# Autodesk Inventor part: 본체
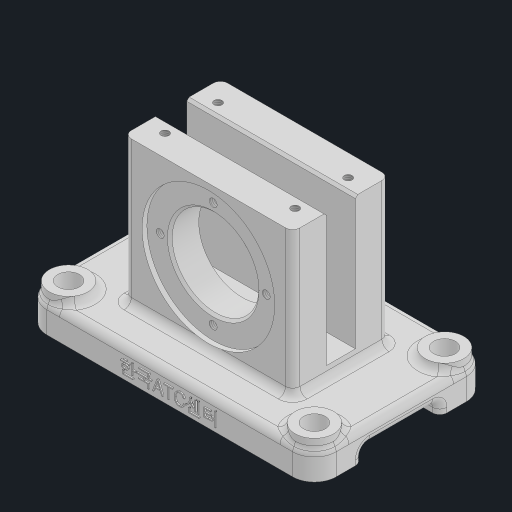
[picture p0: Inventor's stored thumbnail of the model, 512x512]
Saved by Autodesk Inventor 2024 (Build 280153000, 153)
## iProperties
Created: 2025-04
Part Number: 본체
Material: 일반
Document SubType Name: Modeling
Designer: kh_501
Density: 1 g/cm^3
Appearance: 기본값
Author: kh_501
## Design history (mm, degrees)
sketch "스케치1"
  geometry: L1 (-36, 60)-(36, 60); L2 (36, 60)-(36, -60); L3 (36, -60)-(-36, -60); L4 (-36, -60)-(-36, 60); L5 (-36, 60)-(36, -60); L6 (36, 60)-(-36, -60); 1 further point
  constraints: 12 end point, 2 midpoint, 2 parallel, 1 horizontal, 1 perpendicular
  dimensions: "d0" = 72 distance of L2.end L3.end; "d1" = 120 distance of L1.end L2.end
extrude "돌출1" new body sketch "스케치1" distance "d2" = 12; taper "d3" = 0 deg
sketch "스케치2"
  geometry: L1 (20, -35)-(-20, -35); L2 (-20, -35)-(-20, 35); L3 (-20, 35)-(20, 35); L4 (20, 35)-(20, -35); L5 (20, -35)-(-20, 35); L6 (-20, -35)-(20, 35); 1 further point
  constraints: 12 end point, 2 midpoint, 2 parallel, 1 horizontal, 1 perpendicular
  dimensions: "d4" = 40 distance of L2.end L3.end; "d5" = 70 distance of L1.end L2.end
extrude "돌출2" join sketch "스케치2" distance "d6" = 60; taper "d7" = 0 deg
sketch "스케치3"
  geometry: L1 (6, -35)-(-6, -35); L2 (-6, -35)-(-6, 35); L3 (-6, 35)-(6, 35); L4 (6, 35)-(6, -35); L5 (6, -35)-(-6, 35); L6 (-6, -35)-(6, 35); 1 further point
  constraints: 12 end point, 2 midpoint, 2 parallel, 1 horizontal, 1 perpendicular
  dimensions: "d8" = 12 distance of L2.end L3.end; "d9" = 70 distance of L1.end L2.end
extrude "돌출3" cut sketch "스케치3" distance "d10" = 55; taper "d11" = 0 deg
fillet "모깎기1" dims "d12" = 9
sketch "스케치4"
  geometry: C1 r 8 at (-27, -51); C2 r 8 at (27, -51); C3 r 8 at (27, 51); C4 r 8 at (-27, 51); 5 further points
  constraints: 4 centre point, 4 coincident, 2 horizontal alignment, 2 vertical alignment
  dimensions: "d13" = 102 distance of point (-27, 51) point (-27, -51); "d14" = 51 vertical distance of point (0, 0) point (-27, -51) (= 0.5 x d13); "d15" = 54 distance of point (27, -51) point (-27, -51); "d16" = 27 horizontal distance of point (0, 0) point (-27, -51) (= 0.5 x d15); "d17" = 16 diameter of C1; "d18" = 16 diameter of C2; "d19" = 16 diameter of C3; "d20" = 16 diameter of C4
extrude "돌출4" join sketch "스케치4" distance "d21" = 3; taper "d22" = 0 deg
sketch "스케치5"
  geometry: C1 r 8 at (-54, 0) reference; C2 r 8 at (0, 0) reference; C3 r 8 at (0, 102) reference; C4 r 8 at (-54, 102) reference; 5 further points
  constraints: 4 coincident
hole "구멍1" sketch "스케치5" at (-54, 0), (0, 0), (0, 102), (-54, 102) diameter "d23" = 9; stored, may be unused: countersink angle "d27" = 90 deg, drill point angle "d29" = 118 deg; dims "d24" = 12, "d25" = 4, "d26" = 2, "d28" = 15
sketch "스케치6"
  geometry: L1 (20, 12)-(20, 72) reference; L2 (20, 42)-(-27, 42); L3 (-22.5, 0)-(-31.5, 0) reference; L4 (20, 69.5)-(18, 69.5); L5 (18, 69.5)-(18, 60); L6 (18, 60)-(-6, 60); L7 (-6, 60)-(-6, 57); L8 (-6, 57)-(-11, 57); L9 (-11, 57)-(-11, 53); L10 (-11, 53)-(-27, 53); L11 (-27, 53)-(-27, 42); L12 (-6, 17)-(-6, 72) reference; L13 (-20, 12)-(-20, 72) reference; L14 (-20, 59)-(-27, 59); L15 (-27, 59)-(-27, 53); 2 further points
  constraints: 22 end point, 8 perpendicular, 3 horizontal, 3 point on line, 1 midpoint
  dimensions: "d30" = 47 distance of L2.start L2.end; "d31" = 42 distance between parallel lines of L3 L2; "d32" = 22 diameter of L10 L2; "d33" = 5 distance of L7.end L8.end; "d34" = 2 distance of L4.start L4.end; "d35" = 36 diameter of L6 L2; "d36" = 30 diameter of L8 L2; "d37" = 55 diameter of L4 L2; "d38" = 34 diameter of L14 L2
revolve "회전1" stored, may be unused: angle "d39" = 90 deg
revolve "회전2" stored, may be unused: angle "d40" = 90 deg
sketch "스케치7" dims "d41" = 44
  geometry: L1 (0, 0)-(0, 27.5); 3 further points
  constraints: 2 end point, 2 vertical alignment, 1 point on line, 1 vertical, 3 other
hole "구멍2" sketch "스케치7" at (0, 22) diameter "d42" = 3.242; stored, may be unused: countersink angle "d46" = 90 deg, drill point angle "d48" = 118 deg; dims "d43" = 8, "d44" = 4, "d45" = 2, "d47" = 10
sketch "스케치8"
  geometry: 5 further points
  constraints: 2 horizontal alignment, 2 vertical alignment
  dimensions: "d52" = 54 distance of point (-11, 27) point (-11, -27); "d53" = 22 distance of point (11, 27) point (-11, 27); "d54" = 27 vertical distance of point (0, 0) point (-11, -27) (= 0.5 x d52); "d55" = 11 horizontal distance of point (11, 27) point (0, 0) (= 0.5 x d53)
hole "구멍3" sketch "스케치8" at (-11, -27), (-11, 27), (11, 27), (11, -27) diameter "d56" = 3.242; stored, may be unused: countersink angle "d60" = 90 deg, drill point angle "d62" = 118 deg; dims "d57" = 8, "d58" = 4, "d59" = 2, "d61" = 10
fillet "모깎기2" dims "d63" = 3
fillet "모깎기3" dims "d64" = 3
chamfer "모따기1" distance "d65" = 1; stored, may be unused: second distance "d66" = 2, angle "d67" = 45 deg
sketch "스케치9"
  geometry: L1 (11, 0)-(43, 0); L2 (43, 0)-(43, 5); L3 (43, 5)-(11, 5); L4 (11, 5)-(11, 0); L5 (11, 0)-(43, 5); L6 (43, 0)-(11, 5); L7 (0, 0)-(54, 0) reference; 3 further points
  constraints: 12 end point, 4 midpoint, 2 parallel, 1 horizontal, 1 perpendicular
  dimensions: "d68" = 32 distance of L3.end L2.end; "d69" = 5 distance of L2.end L1.end
extrude "돌출5" cut sketch "스케치9" extent not by distance; stored distance "d70" = 0; taper "d71" = 0 deg
fillet "모깎기4" dims "d72" = 3
sketch "스케치10" dims "d0" = 72, "d1" = 120
  geometry: L1 (0, 0)-(102, 0) reference; 4 further points
  constraints: 2 midpoint, 1 vertical alignment, 1 other
  dimensions: "d73" = 5 distance of point (51, 0) point (51, 5)
feature "엠보싱1" sketch "스케치10" dims "d0" = 72, "d1" = 120, "d8" = 12, "d74" = 0.5, "d75" = 0
node "솔리드1"
pattern_circular "원형 패턴1" dims angle "d50" = 360 deg
feature "A9D066F2-1C7D-4E18-AEED-F7BC21143FA4" dims "d23" = 9, "d24" = 12, "d25" = 4, "d26" = 2, "d27" = 90 deg, "d28" = 15, "d29" = 118 deg
